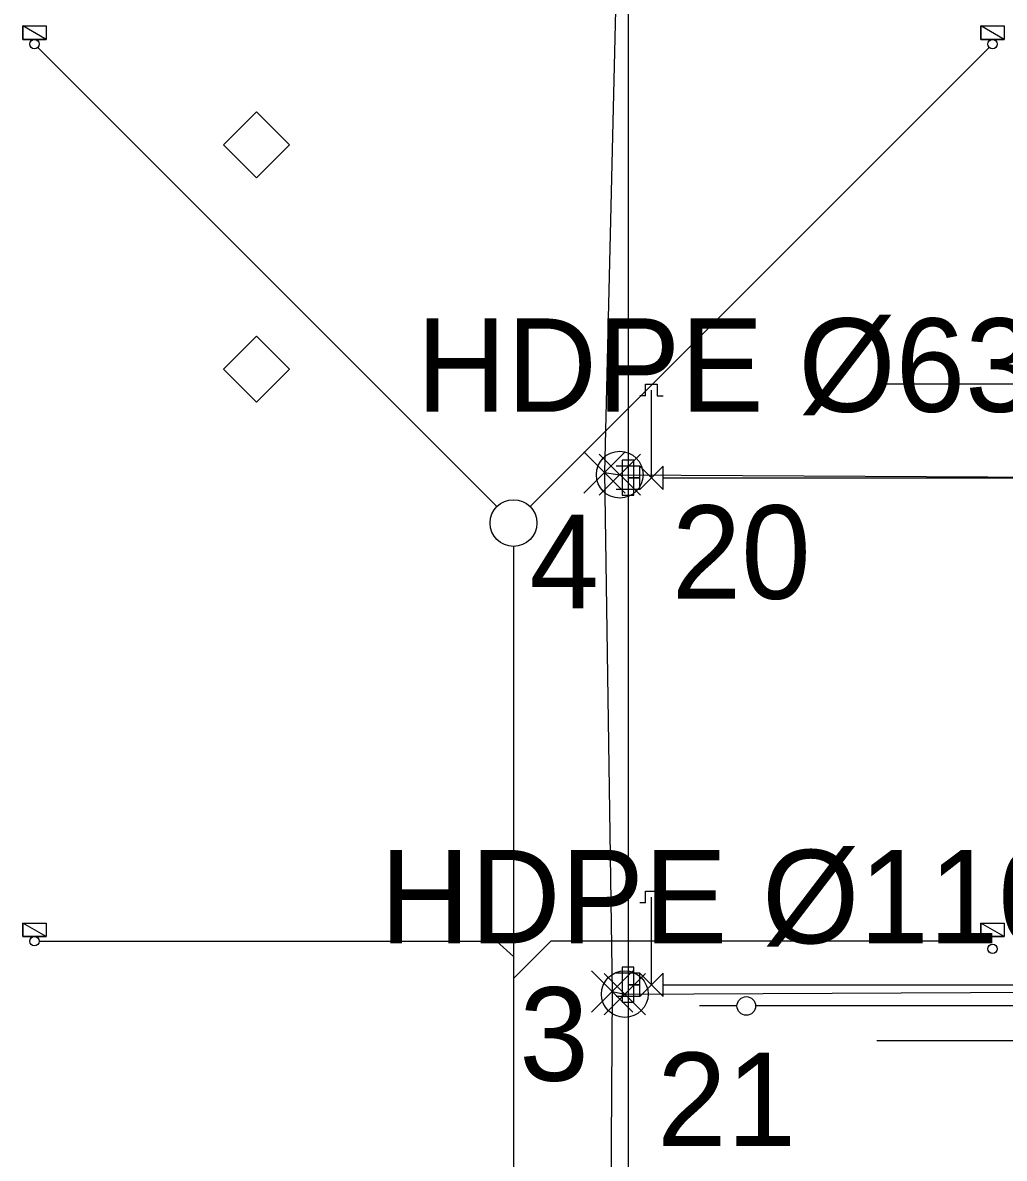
# Model space of a CAD drawing. Extents: x -263964 to -263544, y -1242317 to -1242020.
# Drawn here: x -263937.09 to -263916.09, y -1242121 to -1242096.69 of the extents above; entities that cross this region are included whole.
import ezdxf

# ---------------------------------------------------------------- set-up
doc = ezdxf.new("R2010")
doc.units = 0
for name, color, linetype in [('KFA_KOORDINACNA_SITUACIA_DSP_SEDA', 7, 'Continuous'), ('KFA_SO_50-1-II_BODY', 7, 'Continuous'), ('KFA_SO_50-1-II_SUPATKA', 7, 'Continuous'), ('KFA_SO_50-1-II_VODOVODNE_PRIPOJKY', 7, 'Continuous'), ('KFA_SO_50-2_POZIARNY_VODOVOD_TRASA', 7, 'Continuous'), ('POPIS', 7, 'Continuous')]:
    doc.layers.add(name, color=color, linetype=linetype)

msp = doc.modelspace()

# ---------------------------------------------------------------- linework, layer by layer
at = {"layer": 'KFA_KOORDINACNA_SITUACIA_DSP_SEDA'}
for p, q in [((-263924.143, -1242082.64), (-263924.143, -1242185.14)), ((-263937.093, -1242097.052), (-263937.093, -1242096.762)), ((-263937.093, -1242096.762), (-263936.593, -1242096.762)), ((-263936.593, -1242097.052), (-263937.093, -1242096.762)), ((-263936.593, -1242097.052), (-263937.093, -1242096.762)), ((-263937.093, -1242096.762), (-263937.093, -1242097.052)), ((-263936.593, -1242096.762), (-263936.593, -1242097.052)), ((-263916.593, -1242097.052), (-263916.593, -1242096.762)), ((-263916.593, -1242096.762), (-263916.093, -1242096.762)), ((-263916.093, -1242097.052), (-263916.593, -1242096.762)), ((-263916.093, -1242097.052), (-263916.593, -1242096.762)), ((-263916.593, -1242096.762), (-263916.593, -1242097.052)), ((-263916.093, -1242096.762), (-263916.093, -1242097.052)), ((-263936.593, -1242097.052), (-263937.093, -1242097.052)), ((-263937.093, -1242097.052), (-263936.593, -1242097.052)), ((-263916.093, -1242097.052), (-263916.593, -1242097.052)), ((-263916.593, -1242097.052), (-263916.093, -1242097.052)), ((-263936.772, -1242097.223), (-263926.946, -1242107.049)), ((-263916.414, -1242097.223), (-263926.239, -1242107.049)), ((-263932.8, -1242099.307), (-263932.093, -1242098.6)), ((-263932.093, -1242098.6), (-263931.386, -1242099.307)), ((-263932.093, -1242098.6), (-263932.093, -1242098.6)), ((-263932.093, -1242100.014), (-263932.8, -1242099.307)), ((-263931.386, -1242099.307), (-263932.093, -1242100.014)), ((-263932.8, -1242104.107), (-263932.093, -1242103.4)), ((-263932.093, -1242103.4), (-263931.386, -1242104.107)), ((-263932.093, -1242103.4), (-263932.093, -1242103.4)), ((-263932.093, -1242104.814), (-263932.8, -1242104.107)), ((-263931.386, -1242104.107), (-263932.093, -1242104.814)), ((-263923.768, -1242104.682), (-263923.768, -1242104.432)), ((-263923.768, -1242104.432), (-263923.518, -1242104.432)), ((-263923.518, -1242104.432), (-263923.518, -1242104.682)), ((-263908.718, -1242104.427), (-263918.846, -1242104.427)), ((-263923.768, -1242104.682), (-263923.893, -1242104.682)), ((-263923.643, -1242106.432), (-263923.643, -1242104.557)), ((-263923.518, -1242104.682), (-263923.393, -1242104.682)), ((-263923.893, -1242106.182), (-263924.393, -1242106.182)), ((-263924.018, -1242106.057), (-263924.268, -1242106.057)), ((-263924.268, -1242106.057), (-263924.268, -1242106.807)), ((-263924.018, -1242106.807), (-263924.018, -1242106.057)), ((-263923.893, -1242106.682), (-263923.893, -1242106.182)), ((-263923.893, -1242106.182), (-263923.393, -1242106.682)), ((-263923.393, -1242106.182), (-263923.893, -1242106.682)), ((-263923.393, -1242106.682), (-263923.393, -1242106.182)), ((-263924.143, -1242106.432), (-263923.893, -1242106.432)), ((-263923.893, -1242106.432), (-263924.143, -1242106.432)), ((-263923.393, -1242106.432), (-263903.343, -1242106.432)), ((-263923.893, -1242106.682), (-263924.393, -1242106.682)), ((-263924.268, -1242106.807), (-263924.018, -1242106.807)), ((-263926.593, -1242107.902), (-263926.593, -1242154.252)), ((-263926.593, -1242107.902), (-263926.593, -1242154.252)), ((-263923.768, -1242115.532), (-263923.768, -1242115.282)), ((-263923.768, -1242115.282), (-263923.518, -1242115.282)), ((-263923.643, -1242117.282), (-263923.643, -1242115.407)), ((-263923.518, -1242115.282), (-263923.518, -1242115.532)), ((-263923.768, -1242115.532), (-263923.893, -1242115.532)), ((-263923.518, -1242115.532), (-263923.393, -1242115.532)), ((-263937.093, -1242116.252), (-263937.093, -1242115.962)), ((-263937.093, -1242115.962), (-263936.593, -1242115.962)), ((-263936.593, -1242116.252), (-263937.093, -1242115.962)), ((-263936.593, -1242116.252), (-263937.093, -1242115.962)), ((-263937.093, -1242115.962), (-263937.093, -1242116.252)), ((-263936.593, -1242115.962), (-263936.593, -1242116.252)), ((-263916.593, -1242116.252), (-263916.593, -1242115.962)), ((-263916.593, -1242115.962), (-263916.093, -1242115.962)), ((-263916.093, -1242116.252), (-263916.593, -1242115.962)), ((-263916.093, -1242116.252), (-263916.593, -1242115.962)), ((-263916.593, -1242115.962), (-263916.593, -1242116.252)), ((-263916.093, -1242115.962), (-263916.093, -1242116.252)), ((-263936.593, -1242116.252), (-263937.093, -1242116.252)), ((-263937.093, -1242116.252), (-263936.593, -1242116.252)), ((-263936.743, -1242116.352), (-263926.953, -1242116.352)), ((-263926.953, -1242116.352), (-263926.592, -1242116.677)), ((-263925.797, -1242116.352), (-263926.592, -1242117.147)), ((-263916.443, -1242116.352), (-263925.797, -1242116.352)), ((-263916.093, -1242116.252), (-263916.593, -1242116.252)), ((-263916.593, -1242116.252), (-263916.093, -1242116.252)), ((-263923.893, -1242117.032), (-263924.393, -1242117.032)), ((-263924.018, -1242116.907), (-263924.268, -1242116.907)), ((-263924.268, -1242116.907), (-263924.268, -1242117.657)), ((-263924.018, -1242117.657), (-263924.018, -1242116.907)), ((-263923.893, -1242117.532), (-263923.893, -1242117.032)), ((-263923.893, -1242117.032), (-263923.393, -1242117.532)), ((-263923.393, -1242117.032), (-263923.893, -1242117.532)), ((-263923.393, -1242117.532), (-263923.393, -1242117.032)), ((-263924.143, -1242117.282), (-263923.893, -1242117.282)), ((-263923.893, -1242117.282), (-263924.143, -1242117.282)), ((-263923.393, -1242117.282), (-263906.493, -1242117.282)), ((-263923.893, -1242117.532), (-263924.393, -1242117.532)), ((-263924.268, -1242117.657), (-263924.018, -1242117.657)), ((-263921.812, -1242117.737), (-263922.612, -1242117.737)), ((-263903.343, -1242117.732), (-263921.412, -1242117.737)), ((-263908.718, -1242118.482), (-263918.819, -1242118.482))]:
    msp.add_line(p, q, dxfattribs=at)
for centre, radius in [((-263936.843, -1242097.152), 0.1), ((-263916.343, -1242097.152), 0.1), ((-263926.593, -1242107.402), 0.5), ((-263936.843, -1242116.352), 0.1), ((-263916.343, -1242116.514), 0.1), ((-263921.612, -1242117.737), 0.2)]:
    msp.add_circle(centre, radius, dxfattribs=at)
at = {"layer": 'KFA_SO_50-1-II_BODY'}
for p, q in [((-263925.086, -1242106.764), (-263924.202, -1242105.88)), ((-263924.202, -1242106.764), (-263925.086, -1242105.88)), ((-263924.762, -1242106.809), (-263923.878, -1242105.925)), ((-263923.878, -1242106.809), (-263924.762, -1242105.925)), ((-263924.921, -1242117.869), (-263924.037, -1242116.985)), ((-263924.037, -1242117.869), (-263924.921, -1242116.985)), ((-263924.654, -1242117.925), (-263923.77, -1242117.041)), ((-263923.77, -1242117.925), (-263924.654, -1242117.041))]:
    msp.add_line(p, q, dxfattribs=at)
at = {"layer": 'KFA_SO_50-1-II_SUPATKA'}
for centre in [(-263924.32, -1242106.367), (-263924.212, -1242117.483)]:
    msp.add_circle(centre, 0.5, dxfattribs=at)
at = {"layer": 'KFA_SO_50-1-II_VODOVODNE_PRIPOJKY'}
for points in [[(-263924.644, -1242106.322), (-263924.32, -1242106.367), (-263903.32, -1242106.483)], [(-263924.479, -1242117.427), (-263924.212, -1242117.483), (-263906.466, -1242117.398)]]:
    msp.add_lwpolyline(points, dxfattribs=at)
at = {"layer": 'KFA_SO_50-2_POZIARNY_VODOVOD_TRASA'}
msp.add_lwpolyline([(-263788.062, -1242148.958), (-263787.919, -1242127.952), (-263787.952, -1242110.966), (-263788.129, -1242082.536), (-263828.429, -1242082.723), (-263836.783, -1242082.559), (-263867.306, -1242082.615), (-263886.71, -1242082.472), (-263924.08, -1242082.613), (-263924.644, -1242106.322), (-263924.479, -1242117.427), (-263924.931, -1242185.127)], dxfattribs=at)

# ---------------------------------------------------------------- texts
at = {"layer": 'KFA_SO_50-1-II_BODY'}
for s, p in [('20', (-263923.208, -1242109.024)), ('4', (-263926.252, -1242109.226)), ('3', (-263926.469, -1242119.337)), ('21', (-263923.52, -1242120.734))]:
    msp.add_text(s, height=2, dxfattribs=at).set_placement(p)
at = {"layer": 'POPIS'}
for s, p in [('HDPE Ø63mm - 21,33m', (-263928.671, -1242105.022)), ('HDPE Ø110mm - 18,02m', (-263929.448, -1242116.396))]:
    msp.add_text(s, height=2, dxfattribs=at).set_placement(p)

doc.saveas('drawing.dxf')
